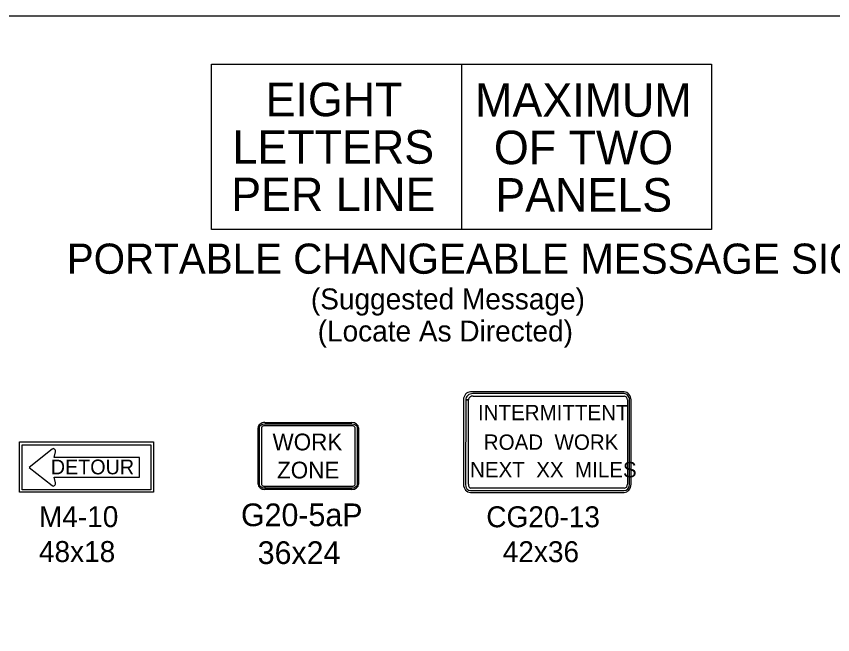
# Model space of a CAD drawing. Extents: x 1458 to 4498, y 17709 to 24109.
# Drawn here: x 2049 to 2634, y 21466 to 21909 of the extents above; entities that cross this region are included whole.
import ezdxf

# ---------------------------------------------------------------- set-up
doc = ezdxf.new("R2010")
doc.units = 0
doc.layers.add('P_TRAF_TCP_General', color=7, linetype='Continuous')

msp = doc.modelspace()

# ---------------------------------------------------------------- linework, layer by layer
at = {"layer": 'P_TRAF_TCP_General'}
for p, q in [((2367.93, 21874.81), (2367.93, 21756.39)), ((2484.24, 21640.23), (2374.35, 21640.23)), ((2484.24, 21638.98), (2375.93, 21638.98)), ((2376.25, 21637.23), (2484.24, 21637.23)), ((2369.32, 21634.48), (2369.32, 21574.01)), ((2370.96, 21634.47), (2370.76, 21574.01)), ((2370.96, 21634.46), (2372.83, 21634.47)), ((2372.83, 21634.47), (2370.96, 21634.47)), ((2372.83, 21574.01), (2372.83, 21634.47)), ((2486.65, 21634.48), (2486.65, 21574.01)), ((2488.18, 21574.01), (2488.18, 21634.48)), ((2489.27, 21574.01), (2489.27, 21634.48)), ((2222.26, 21574.09), (2222.26, 21614.47)), ((2223.22, 21574.09), (2223.22, 21614.47)), ((2224.66, 21614.47), (2224.66, 21574.09)), ((2227.01, 21618.27), (2289.47, 21618.27)), ((2227.01, 21617.31), (2289.47, 21617.31)), ((2289.47, 21615.87), (2227.01, 21615.87)), ((2291.82, 21574.09), (2291.82, 21614.47)), ((2293.26, 21614.47), (2293.26, 21574.09)), ((2294.22, 21614.47), (2294.22, 21574.09)), ((2074.76, 21599.24), (2058.34, 21586.17)), ((2076.19, 21593.24), (2077.16, 21597.17)), ((2137.31, 21593.24), (2076.19, 21593.24)), ((2137.31, 21579.1), (2137.31, 21593.24)), ((2058.34, 21586.17), (2074.75, 21573.11)), ((2077.17, 21575.15), (2076.19, 21579.1)), ((2076.19, 21579.1), (2137.31, 21579.1)), ((2227.01, 21572.69), (2227.01, 21571.25)), ((2227.01, 21572.69), (2289.47, 21572.69)), ((2289.47, 21571.25), (2227.01, 21571.25)), ((2289.47, 21570.29), (2227.01, 21570.29)), ((2374.3, 21569.51), (2484.24, 21569.51)), ((2374.35, 21568.26), (2484.24, 21568.26)), ((2484.24, 21571.26), (2374.36, 21571.26))]:
    msp.add_line(p, q, dxfattribs=at)
for points in [[(4498.44, 21909.14), (1458.44, 21909.14), (1458.44, 19909.14), (4498.44, 19909.14)], [(2189.02, 21874.81), (2546.84, 21874.81), (2546.84, 21756.39), (2189.02, 21756.39)], [(2051.36, 21604.35), (2147.33, 21604.35), (2147.33, 21568.36), (2051.36, 21568.36)], [(2145.47, 21570.17), (2053.44, 21570.17), (2053.44, 21602.28), (2145.47, 21602.28)]]:
    msp.add_lwpolyline(points, close=True, dxfattribs=at)
for centre, major_axis, ratio, start_param, end_param in [((2374.35, 21634.48), (0, -5.75), 0.875, 3.141593, 4.712389), ((2375.93, 21634.46), (4.97, 0), 0.908446, 1.570796, 3.141593), ((2376.25, 21634.47), (3.41, 0), 0.811046, 1.570796, 3.141593), ((2484.24, 21634.48), (0, -5.75), 0.875, 1.570796, 3.141593), ((2484.24, 21634.48), (0, -4.5), 0.875, 1.570796, 3.141593), ((2484.24, 21634.48), (0, -2.75), 0.875, 1.570796, 3.141593), ((2227.01, 21614.47), (4.75, 0), 0.8, 1.570796, 3.141593), ((2289.47, 21614.47), (4.75, 0), 0.8, 0, 1.570796), ((2075.64, 21597.69), (0, 1.86), 0.851337, 4.429862, 6.871525), ((2075.64, 21574.66), (0, -1.86), 0.851337, 5.687791, 8.124104), ((2227.01, 21574.09), (4.75, 0), 0.8, 3.141593, 4.712389), ((2289.47, 21574.09), (4.75, 0), 0.8, 4.712389, 6.283185), ((2374.35, 21574.01), (0, -5.75), 0.875, 4.712389, 6.283185), ((2374.3, 21574.01), (0, -4.5), 0.788416, 4.712389, 6.283185), ((2374.36, 21574.01), (0, -2.75), 0.555751, 4.712389, 6.283185), ((2484.24, 21574.01), (0, -4.5), 0.875, 0, 1.570796), ((2484.24, 21574.01), (0, -2.75), 0.875, 0, 1.570796), ((2484.24, 21574.01), (0, -5.75), 0.875, 0, 1.570796)]:
    msp.add_ellipse(centre, major_axis=major_axis, ratio=ratio, start_param=start_param, end_param=end_param, dxfattribs=at)
for points in [[(2223.22, 21614.47), (2223.22, 21615.2), (2223.58, 21615.87), (2224.93, 21616.95), (2225.91, 21617.31), (2227.01, 21617.31)], [(2227.01, 21615.87), (2226.22, 21615.87), (2225.54, 21615.59), (2224.96, 21615.13), (2224.82, 21614.96), (2224.69, 21614.7), (2224.66, 21614.6), (2224.66, 21614.47)], [(2289.47, 21617.31), (2290.58, 21617.31), (2291.56, 21616.95), (2292.9, 21615.87), (2293.26, 21615.2), (2293.26, 21614.47)], [(2291.82, 21614.47), (2291.82, 21614.72), (2291.74, 21614.96), (2290.92, 21615.61), (2290.26, 21615.87), (2289.47, 21615.87)], [(2227.01, 21571.25), (2225.91, 21571.25), (2224.93, 21571.61), (2223.58, 21572.69), (2223.22, 21573.37), (2223.22, 21574.09)], [(2224.66, 21574.09), (2224.66, 21573.84), (2224.74, 21573.61), (2225.56, 21572.95), (2226.22, 21572.69), (2227.01, 21572.69)], [(2293.26, 21574.09), (2293.26, 21573.37), (2292.9, 21572.69), (2291.56, 21571.61), (2290.58, 21571.25), (2289.47, 21571.25)], [(2289.47, 21572.69), (2290.26, 21572.69), (2290.94, 21572.97), (2291.53, 21573.43), (2291.66, 21573.6), (2291.8, 21573.86), (2291.82, 21573.96), (2291.82, 21574.09)]]:
    msp.add_open_spline(points, degree=3, dxfattribs=at)

# ---------------------------------------------------------------- texts
for s, height, p in [('EIGHT', 23.99, (2227.6, 21837.59)), ('MAXIMUM', 23.99, (2377.64, 21837.25)), ('LETTERS', 23.99, (2203.91, 21803.6)), ('OF TWO', 23.99, (2391.11, 21803.26)), ('PER LINE', 23.99, (2203, 21769.62)), ('PANELS', 23.99, (2392.12, 21769.28)), ('PORTABLE CHANGEABLE MESSAGE SIGN', 21.6, (2085.3, 21724.8)), ('(Suggested Message)', 14.994, (2260.08, 21699.28)), ('(Locate As Directed)', 14.994, (2264.94, 21676.29)), ('INTERMITTENT', 10.9956, (2379.67, 21619.94)), ('WORK', 12, (2232.62, 21598.34)), ('ROAD  WORK', 10.996, (2383.84, 21598.72)), ('DETOUR', 10.56, (2073.86, 21581.17)), ('ZONE', 12, (2235.84, 21578.22)), ('NEXT  XX  MILES', 10.9956, (2374.01, 21579.03)), ('M4-10', 14.994, (2065.37, 21543.37)), ('G20-5aP', 16.25, (2210.05, 21544.04)), ('CG20-13', 14.994, (2385.65, 21543.27)), ('48x18', 14.994, (2065.37, 21518.38)), ('36x24', 16.25, (2221.99, 21516.96)), ('42x36', 14.994, (2397.43, 21518.28))]:
    msp.add_text(s, height=height, dxfattribs=at).set_placement(p)

doc.saveas('drawing.dxf')
